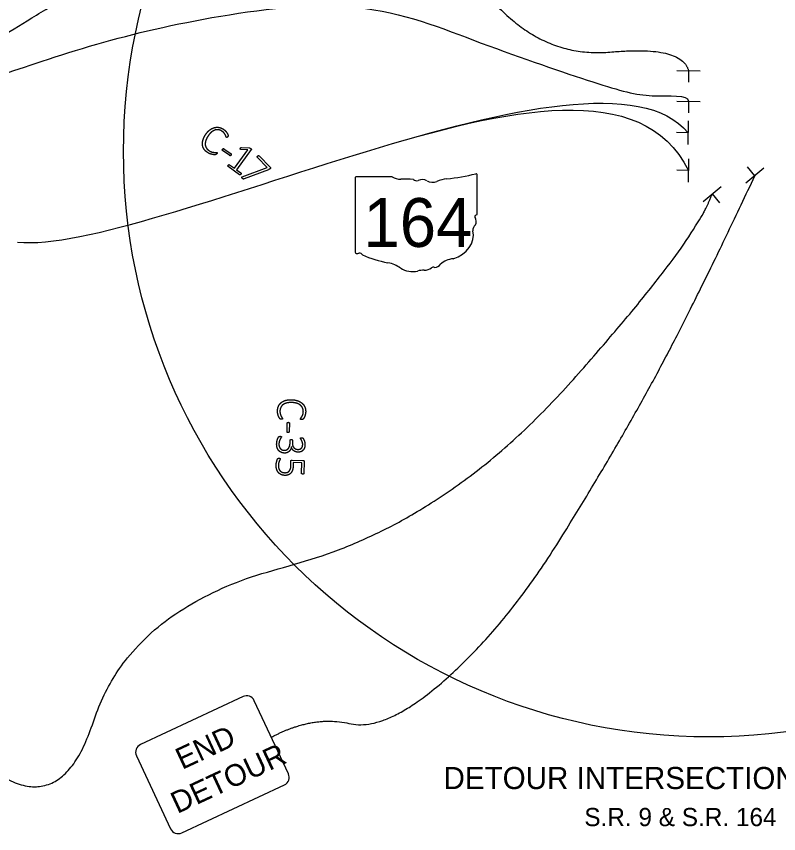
# Model space of a CAD drawing. Extents: x 0 to 1214, y 0 to 883.
# Drawn here: x 83.6 to 200.8, y 223.3 to 349 of the extents above; entities that cross this region are included whole.
import ezdxf

# ---------------------------------------------------------------- set-up
doc = ezdxf.new("R2010")
doc.units = 0
for name, color, linetype in [('GM_X_Major_Lake', 7, 'Continuous'), ('GM_X_Minor_River', 7, 'Continuous'), ('GM_X_Section', 7, 'Continuous'), ('GM_X_Township_Road_Text', 7, 'Continuous'), ('SH_Data', 7, 'Continuous')]:
    doc.layers.add(name, color=color, linetype=linetype)

msp = doc.modelspace()

# ---------------------------------------------------------------- linework, layer by layer
at = {"layer": 'GM_X_Major_Lake'}
for p, q in [((116.39, 327.55), (115.28, 328.35)), ((115.47, 328.61), (116.58, 327.81)), ((118.21, 328.81), (119.42, 328.74)), ((114.4, 327.84), (114.4, 327.84)), ((116.57, 327.63), (116.57, 327.63)), ((120.9, 327.52), (122.6, 325.77)), ((117.89, 324.62), (116.15, 325.88)), ((122.58, 325.54), (122.58, 325.54)), ((118.08, 324.69), (118.08, 324.69)), ((122.33, 325.38), (118.58, 323.97)), ((124.32, 287.02), (124.32, 287.02)), ((125.2, 285.08), (125.23, 286.46)), ((125.56, 286.45), (125.52, 285.08)), ((125.36, 284.98), (125.36, 284.98)), ((125.66, 283.37), (125.67, 283.79)), ((125.87, 282.81), (125.86, 282.81)), ((126.02, 283.78), (126.01, 283.41)), ((124.82, 281.82), (124.82, 281.82)), ((125.98, 280.74), (127.64, 280.7)), ((127.83, 280.51), (127.79, 278.7)), ((124.89, 278.39), (124.89, 278.39))]:
    msp.add_line(p, q, dxfattribs=at)
for points in [[(116.35, 326.15), (117.11, 325.6), (119.15, 328.42), (118.1, 328.5)], [(119.69, 328.48), (117.44, 325.36), (118.09, 324.89)], [(118.3, 324.29), (122.16, 325.72), (120.64, 327.27)], [(127.43, 278.71), (127.47, 280.33), (126.12, 280.36)]]:
    msp.add_lwpolyline(points, dxfattribs=at)
for points in [[(113.27, 331.46), (113.6, 331.73), (113.96, 331.84)], [(113.96, 331.84), (114.31, 331.95), (114.68, 331.9)], [(114.68, 331.9), (115.04, 331.85), (115.38, 331.63)], [(112.27, 329.93), (112.38, 330.32), (112.65, 330.75)], [(112.65, 330.75), (112.93, 331.18), (113.27, 331.46)], [(113.03, 330.53), (112.8, 330.18), (112.7, 329.85)], [(113.54, 331.14), (113.27, 330.91), (113.03, 330.53)], [(114.09, 331.47), (113.81, 331.37), (113.54, 331.14)], [(114.64, 331.53), (114.36, 331.56), (114.09, 331.47)], [(115.16, 331.33), (114.91, 331.49), (114.64, 331.53)], [(115.52, 331.02), (115.39, 331.18), (115.16, 331.33)], [(115.38, 331.63), (115.54, 331.52), (115.67, 331.4)], [(115.72, 330.71), (115.65, 330.86), (115.52, 331.02)], [(115.67, 331.4), (115.8, 331.27), (115.89, 331.14)], [(115.82, 330.47), (115.79, 330.57), (115.72, 330.71)], [(115.89, 330.34), (115.85, 330.37), (115.82, 330.47)], [(115.89, 331.14), (115.99, 331.01), (116.05, 330.88)], [(116.07, 330.45), (116.04, 330.42), (116.02, 330.39)], [(116.05, 330.88), (116.11, 330.76), (116.12, 330.7)], [(116.1, 330.52), (116.09, 330.49), (116.07, 330.45)], [(116.13, 330.57), (116.12, 330.54), (116.1, 330.52)], [(116.12, 330.7), (116.14, 330.64), (116.14, 330.61)], [(116.14, 330.61), (116.13, 330.59), (116.13, 330.57)], [(112.2, 329.18), (112.16, 329.53), (112.27, 329.93)], [(112.7, 329.85), (112.6, 329.53), (112.62, 329.25)], [(112.62, 329.25), (112.64, 328.96), (112.79, 328.73)], [(115.93, 330.33), (115.91, 330.33), (115.89, 330.34)], [(115.98, 330.35), (115.95, 330.33), (115.93, 330.33)], [(116.02, 330.39), (116, 330.36), (115.98, 330.35)], [(112.44, 328.54), (112.24, 328.83), (112.2, 329.18)], [(112.97, 328.03), (112.64, 328.24), (112.44, 328.54)], [(112.79, 328.73), (112.94, 328.49), (113.22, 328.31)], [(113.38, 327.82), (113.18, 327.89), (112.97, 328.03)], [(113.22, 328.31), (113.44, 328.17), (113.64, 328.11)], [(113.64, 328.11), (113.84, 328.06), (114.01, 328.05)], [(114.01, 328.05), (114.17, 328.05), (114.28, 328.05)], [(114.28, 328.05), (114.39, 328.06), (114.44, 328.03)], [(114.44, 328.03), (114.45, 328.02), (114.46, 328.01)], [(114.46, 327.97), (114.46, 327.95), (114.44, 327.92)], [(114.46, 328.01), (114.47, 328), (114.46, 327.97)], [(115.24, 328.42), (115.24, 328.46), (115.29, 328.54)], [(115.28, 328.35), (115.24, 328.37), (115.24, 328.42)], [(115.29, 328.54), (115.34, 328.61), (115.39, 328.63)], [(115.39, 328.63), (115.43, 328.64), (115.47, 328.61)], [(117.97, 328.56), (117.97, 328.59), (117.98, 328.62)], [(118.01, 328.52), (117.98, 328.54), (117.97, 328.56)], [(117.98, 328.62), (118, 328.65), (118.03, 328.7)], [(118.1, 328.5), (118.04, 328.51), (118.01, 328.52)], [(118.03, 328.7), (118.06, 328.73), (118.08, 328.75)], [(118.08, 328.75), (118.1, 328.78), (118.12, 328.79)], [(118.12, 328.79), (118.14, 328.8), (118.16, 328.81)], [(118.16, 328.81), (118.18, 328.81), (118.21, 328.81)], [(119.42, 328.74), (119.43, 328.74), (119.45, 328.74)], [(119.45, 328.74), (119.46, 328.73), (119.48, 328.73)], [(119.48, 328.73), (119.51, 328.72), (119.53, 328.7)], [(119.53, 328.7), (119.55, 328.69), (119.58, 328.67)], [(119.58, 328.67), (119.62, 328.63), (119.65, 328.61)], [(119.65, 328.61), (119.68, 328.58), (119.69, 328.56)], [(119.69, 328.56), (119.71, 328.53), (119.71, 328.52)], [(119.71, 328.52), (119.7, 328.5), (119.69, 328.48)], [(113.75, 327.72), (113.58, 327.75), (113.38, 327.82)], [(114.05, 327.69), (113.92, 327.69), (113.75, 327.72)], [(114.22, 327.7), (114.18, 327.69), (114.05, 327.69)], [(114.28, 327.72), (114.26, 327.71), (114.22, 327.7)], [(114.32, 327.75), (114.3, 327.73), (114.28, 327.72)], [(114.36, 327.79), (114.34, 327.76), (114.32, 327.75)], [(114.4, 327.84), (114.38, 327.81), (114.36, 327.79)], [(114.44, 327.92), (114.42, 327.88), (114.4, 327.84)], [(116.47, 327.54), (116.43, 327.52), (116.39, 327.55)], [(116.57, 327.63), (116.51, 327.55), (116.47, 327.54)], [(116.61, 327.69), (116.59, 327.66), (116.57, 327.63)], [(116.58, 327.81), (116.6, 327.8), (116.61, 327.79)], [(116.61, 327.79), (116.62, 327.77), (116.62, 327.74)], [(116.62, 327.74), (116.62, 327.72), (116.61, 327.69)], [(120.64, 327.27), (120.6, 327.32), (120.62, 327.37)], [(120.62, 327.37), (120.63, 327.43), (120.69, 327.49)], [(120.69, 327.49), (120.72, 327.52), (120.75, 327.53)], [(120.75, 327.53), (120.77, 327.55), (120.8, 327.55)], [(120.8, 327.55), (120.83, 327.56), (120.85, 327.55)], [(120.85, 327.55), (120.88, 327.54), (120.9, 327.52)], [(116.11, 325.95), (116.11, 325.97), (116.12, 326)], [(116.13, 325.91), (116.12, 325.92), (116.11, 325.95)], [(116.12, 326), (116.13, 326.04), (116.16, 326.07)], [(116.15, 325.88), (116.14, 325.89), (116.13, 325.91)], [(116.16, 326.07), (116.18, 326.11), (116.21, 326.13)], [(116.21, 326.13), (116.24, 326.15), (116.26, 326.16)], [(116.26, 326.16), (116.28, 326.17), (116.31, 326.16)], [(116.31, 326.16), (116.33, 326.16), (116.35, 326.15)], [(122.47, 325.45), (122.44, 325.43), (122.41, 325.42)], [(122.52, 325.49), (122.5, 325.47), (122.47, 325.45)], [(122.58, 325.54), (122.55, 325.51), (122.52, 325.49)], [(122.63, 325.6), (122.61, 325.57), (122.58, 325.54)], [(122.6, 325.77), (122.63, 325.74), (122.64, 325.71)], [(122.65, 325.66), (122.65, 325.63), (122.63, 325.6)], [(122.64, 325.71), (122.66, 325.69), (122.65, 325.66)], [(117.93, 324.6), (117.91, 324.61), (117.89, 324.62)], [(117.98, 324.6), (117.95, 324.6), (117.93, 324.6)], [(118.03, 324.63), (118, 324.61), (117.98, 324.6)], [(118.08, 324.69), (118.05, 324.65), (118.03, 324.63)], [(118.12, 324.75), (118.1, 324.72), (118.08, 324.69)], [(118.09, 324.89), (118.11, 324.88), (118.12, 324.85)], [(118.12, 324.85), (118.13, 324.83), (118.13, 324.81)], [(118.13, 324.81), (118.13, 324.78), (118.12, 324.75)], [(118.22, 324.22), (118.22, 324.25), (118.24, 324.26)], [(118.24, 324.16), (118.22, 324.19), (118.22, 324.22)], [(118.24, 324.26), (118.27, 324.28), (118.3, 324.29)], [(122.41, 325.42), (122.37, 325.4), (122.33, 325.38)], [(118.31, 324.07), (118.26, 324.12), (118.24, 324.16)], [(118.39, 324), (118.35, 324.02), (118.31, 324.07)], [(118.45, 323.96), (118.42, 323.97), (118.39, 324)], [(118.51, 323.95), (118.48, 323.95), (118.45, 323.96)], [(118.58, 323.97), (118.54, 323.95), (118.51, 323.95)], [(123.73, 288.33), (123.74, 288.73), (123.89, 289.05)], [(123.89, 289.05), (124.04, 289.37), (124.31, 289.59)], [(124.59, 289.27), (124.36, 289.1), (124.24, 288.85)], [(124.31, 289.59), (124.59, 289.81), (124.98, 289.93)], [(125.15, 289.52), (124.82, 289.44), (124.59, 289.27)], [(124.98, 289.93), (125.38, 290.04), (125.88, 290.03)], [(125.9, 289.59), (125.48, 289.6), (125.15, 289.52)], [(125.88, 290.03), (126.4, 290.01), (126.81, 289.87)], [(126.68, 289.48), (126.34, 289.58), (125.9, 289.59)], [(127.25, 289.18), (127.02, 289.37), (126.68, 289.48)], [(126.81, 289.87), (127.22, 289.73), (127.5, 289.49)], [(127.59, 288.75), (127.48, 289), (127.25, 289.18)], [(127.5, 289.49), (127.78, 289.24), (127.93, 288.91)], [(123.77, 287.87), (123.73, 288.08), (123.73, 288.33)], [(123.88, 287.5), (123.82, 287.66), (123.77, 287.87)], [(124.24, 288.85), (124.11, 288.59), (124.1, 288.27)], [(124.1, 288.27), (124.1, 288), (124.16, 287.8)], [(124.16, 287.8), (124.22, 287.6), (124.3, 287.46)], [(127.46, 287.4), (127.55, 287.53), (127.62, 287.73)], [(127.7, 288.2), (127.7, 288.49), (127.59, 288.75)], [(127.62, 287.73), (127.69, 287.92), (127.7, 288.2)], [(128.01, 287.8), (127.97, 287.62), (127.92, 287.47)], [(127.93, 288.91), (128.07, 288.57), (128.06, 288.17)], [(128.06, 288.17), (128.06, 287.98), (128.01, 287.8)], [(124.01, 287.24), (123.95, 287.34), (123.88, 287.5)], [(124.11, 287.1), (124.08, 287.13), (124.01, 287.24)], [(124.16, 287.05), (124.14, 287.06), (124.11, 287.1)], [(124.2, 287.03), (124.18, 287.04), (124.16, 287.05)], [(124.26, 287.02), (124.23, 287.03), (124.2, 287.03)], [(124.32, 287.02), (124.29, 287.02), (124.26, 287.02)], [(124.3, 287.46), (124.38, 287.32), (124.44, 287.23)], [(124.41, 287.02), (124.37, 287.02), (124.32, 287.02)], [(124.47, 287.03), (124.45, 287.02), (124.41, 287.02)], [(124.44, 287.23), (124.51, 287.13), (124.51, 287.09)], [(124.5, 287.05), (124.49, 287.04), (124.47, 287.03)], [(124.51, 287.09), (124.51, 287.07), (124.5, 287.05)], [(125.23, 286.46), (125.23, 286.5), (125.27, 286.53)], [(125.27, 286.53), (125.3, 286.55), (125.4, 286.55)], [(125.4, 286.55), (125.49, 286.55), (125.52, 286.52)], [(125.52, 286.52), (125.56, 286.49), (125.56, 286.45)], [(127.24, 287.06), (127.24, 287.1), (127.31, 287.18)], [(127.25, 287.02), (127.24, 287.03), (127.24, 287.06)], [(127.29, 286.99), (127.26, 287), (127.25, 287.02)], [(127.34, 286.97), (127.31, 286.98), (127.29, 286.99)], [(127.31, 287.18), (127.38, 287.27), (127.46, 287.4)], [(127.42, 286.96), (127.38, 286.96), (127.34, 286.97)], [(127.5, 286.97), (127.46, 286.96), (127.42, 286.96)], [(127.55, 286.97), (127.53, 286.97), (127.5, 286.97)], [(127.6, 286.99), (127.58, 286.98), (127.55, 286.97)], [(127.66, 287.04), (127.62, 287), (127.6, 286.99)], [(127.78, 287.21), (127.71, 287.09), (127.66, 287.04)], [(127.92, 287.47), (127.86, 287.32), (127.78, 287.21)], [(123.65, 283.65), (123.69, 283.84), (123.74, 283.98)], [(123.74, 283.98), (123.79, 284.12), (123.85, 284.21)], [(123.85, 284.21), (123.9, 284.31), (123.92, 284.33)], [(123.92, 284.33), (123.94, 284.35), (123.96, 284.36)], [(123.96, 284.36), (123.98, 284.37), (124, 284.38)], [(124, 284.38), (124.03, 284.39), (124.07, 284.39)], [(124.14, 283.97), (124.07, 283.82), (124.01, 283.64)], [(124.07, 284.39), (124.1, 284.4), (124.16, 284.4)], [(124.27, 284.2), (124.21, 284.11), (124.14, 283.97)], [(124.16, 284.4), (124.26, 284.39), (124.29, 284.37)], [(124.33, 284.31), (124.32, 284.28), (124.27, 284.2)], [(124.29, 284.37), (124.33, 284.35), (124.33, 284.31)], [(125.23, 285.01), (125.2, 285.04), (125.2, 285.08)], [(125.36, 284.98), (125.26, 284.99), (125.23, 285.01)], [(125.44, 284.99), (125.4, 284.98), (125.36, 284.98)], [(125.49, 285.01), (125.47, 284.99), (125.44, 284.99)], [(125.52, 285.04), (125.51, 285.02), (125.49, 285.01)], [(125.52, 285.08), (125.52, 285.06), (125.52, 285.04)], [(127.25, 284.11), (127.25, 284.13), (127.26, 284.14)], [(127.31, 283.99), (127.25, 284.08), (127.25, 284.11)], [(127.26, 284.14), (127.26, 284.16), (127.28, 284.17)], [(127.28, 284.17), (127.3, 284.18), (127.34, 284.19)], [(127.43, 283.78), (127.36, 283.91), (127.31, 283.99)], [(127.34, 284.19), (127.37, 284.19), (127.43, 284.19)], [(127.43, 284.19), (127.47, 284.19), (127.49, 284.19)], [(127.49, 284.19), (127.52, 284.18), (127.54, 284.17)], [(127.54, 284.17), (127.57, 284.16), (127.59, 284.15)], [(127.59, 284.15), (127.61, 284.13), (127.64, 284.1)], [(127.64, 284.1), (127.67, 284.07), (127.72, 283.98)], [(127.72, 283.98), (127.78, 283.89), (127.83, 283.75)], [(123.6, 283.26), (123.6, 283.47), (123.65, 283.65)], [(123.68, 282.65), (123.59, 282.91), (123.6, 283.26)], [(124.01, 283.64), (123.95, 283.45), (123.95, 283.22)], [(123.95, 283.22), (123.94, 282.99), (124, 282.81)], [(124, 282.81), (124.06, 282.63), (124.17, 282.51)], [(125.4, 282.54), (125.52, 282.68), (125.59, 282.89)], [(125.59, 282.89), (125.66, 283.11), (125.66, 283.37)], [(125.67, 283.79), (125.67, 283.81), (125.68, 283.83)], [(125.68, 283.83), (125.69, 283.85), (125.72, 283.87)], [(125.72, 283.87), (125.74, 283.89), (125.77, 283.9)], [(125.86, 282.81), (125.84, 282.59), (125.75, 282.41)], [(125.77, 283.9), (125.8, 283.91), (125.85, 283.91)], [(125.85, 283.91), (125.9, 283.91), (125.93, 283.9)], [(125.99, 282.46), (125.9, 282.61), (125.87, 282.81)], [(125.93, 283.9), (125.96, 283.89), (125.98, 283.87)], [(125.98, 283.87), (126, 283.85), (126.01, 283.83)], [(126.01, 283.83), (126.02, 283.81), (126.02, 283.78)], [(126.01, 283.41), (126, 283.18), (126.06, 282.99)], [(126.06, 282.99), (126.12, 282.81), (126.23, 282.67)], [(127.38, 282.56), (127.48, 282.65), (127.54, 282.79)], [(127.55, 283.49), (127.5, 283.66), (127.43, 283.78)], [(127.54, 282.79), (127.6, 282.94), (127.6, 283.13)], [(127.6, 283.13), (127.61, 283.33), (127.55, 283.49)], [(127.83, 283.75), (127.88, 283.62), (127.92, 283.45)], [(127.95, 283.08), (127.94, 282.79), (127.86, 282.58)], [(127.92, 283.45), (127.95, 283.28), (127.95, 283.08)], [(123.92, 282.2), (123.76, 282.38), (123.68, 282.65)], [(124.31, 281.92), (124.09, 282.02), (123.92, 282.2)], [(124.17, 282.51), (124.28, 282.38), (124.43, 282.32)], [(124.82, 281.82), (124.54, 281.83), (124.31, 281.92)], [(124.43, 282.32), (124.59, 282.25), (124.77, 282.25)], [(124.77, 282.25), (124.97, 282.24), (125.13, 282.32)], [(125.2, 281.89), (125.02, 281.81), (124.82, 281.82)], [(125.13, 282.32), (125.29, 282.39), (125.4, 282.54)], [(125.52, 282.09), (125.38, 281.96), (125.2, 281.89)], [(125.75, 282.41), (125.66, 282.23), (125.52, 282.09)], [(126.21, 282.2), (126.07, 282.3), (125.99, 282.46)], [(126.52, 282.03), (126.34, 282.09), (126.21, 282.2)], [(126.23, 282.67), (126.35, 282.54), (126.51, 282.47)], [(126.51, 282.47), (126.67, 282.39), (126.87, 282.39)], [(126.89, 281.97), (126.69, 281.97), (126.52, 282.03)], [(126.87, 282.39), (127.01, 282.38), (127.15, 282.43)], [(127.3, 282.02), (127.11, 281.96), (126.89, 281.97)], [(127.15, 282.43), (127.28, 282.47), (127.38, 282.56)], [(127.63, 282.23), (127.49, 282.09), (127.3, 282.02)], [(127.86, 282.58), (127.78, 282.36), (127.63, 282.23)], [(123.52, 279.96), (123.53, 280.16), (123.56, 280.33)], [(123.56, 280.33), (123.6, 280.51), (123.64, 280.65)], [(123.64, 280.65), (123.68, 280.78), (123.73, 280.87)], [(123.73, 280.87), (123.77, 280.95), (123.79, 280.98)], [(123.79, 280.98), (123.81, 281), (123.83, 281.01)], [(123.83, 281.01), (123.84, 281.01), (123.87, 281.02)], [(123.87, 281.02), (123.89, 281.03), (123.92, 281.03)], [(123.92, 280.35), (123.87, 280.17), (123.87, 279.93)], [(123.92, 281.03), (123.95, 281.03), (123.99, 281.03)], [(124.02, 280.65), (123.97, 280.53), (123.92, 280.35)], [(123.99, 281.03), (124.03, 281.03), (124.06, 281.02)], [(124.12, 280.84), (124.08, 280.77), (124.02, 280.65)], [(124.06, 281.02), (124.1, 281.02), (124.12, 281.01)], [(124.12, 281.01), (124.14, 280.99), (124.15, 280.98)], [(124.16, 280.94), (124.16, 280.91), (124.12, 280.84)], [(124.15, 280.98), (124.16, 280.96), (124.16, 280.94)], [(125.77, 280.58), (125.78, 280.66), (125.82, 280.7)], [(125.79, 280.32), (125.77, 280.46), (125.77, 280.58)], [(125.8, 279.98), (125.81, 280.18), (125.79, 280.32)], [(125.82, 280.7), (125.86, 280.74), (125.98, 280.74)], [(126.12, 280.36), (126.14, 280.25), (126.14, 280.12)], [(127.64, 280.7), (127.74, 280.7), (127.78, 280.64)], [(127.78, 280.64), (127.83, 280.59), (127.83, 280.51)], [(123.6, 279.33), (123.51, 279.62), (123.52, 279.96)], [(123.86, 278.84), (123.69, 279.05), (123.6, 279.33)], [(123.87, 279.93), (123.86, 279.69), (123.91, 279.49)], [(123.91, 279.49), (123.97, 279.29), (124.09, 279.14)], [(124.09, 279.14), (124.21, 278.99), (124.4, 278.9)], [(125.26, 278.87), (125.44, 278.94), (125.55, 279.08)], [(125.55, 279.08), (125.67, 279.23), (125.73, 279.45)], [(125.73, 279.45), (125.8, 279.67), (125.8, 279.98)], [(126.03, 279.18), (125.93, 278.91), (125.77, 278.73)], [(126.13, 279.83), (126.13, 279.46), (126.03, 279.18)], [(126.14, 280.12), (126.14, 280), (126.13, 279.83)], [(124.3, 278.51), (124.04, 278.63), (123.86, 278.84)], [(124.89, 278.39), (124.55, 278.4), (124.3, 278.51)], [(124.4, 278.9), (124.59, 278.81), (124.86, 278.81)], [(124.86, 278.81), (125.09, 278.8), (125.26, 278.87)], [(125.38, 278.47), (125.15, 278.38), (124.89, 278.39)], [(125.77, 278.73), (125.6, 278.55), (125.38, 278.47)], [(127.48, 278.62), (127.43, 278.65), (127.43, 278.71)], [(127.61, 278.59), (127.53, 278.59), (127.48, 278.62)], [(127.69, 278.59), (127.65, 278.59), (127.61, 278.59)], [(127.74, 278.62), (127.72, 278.6), (127.69, 278.59)], [(127.78, 278.65), (127.76, 278.63), (127.74, 278.62)], [(127.79, 278.7), (127.79, 278.68), (127.78, 278.65)]]:
    msp.add_open_spline(points, degree=2, dxfattribs=at)
at = {"layer": 'GM_X_Minor_River'}
for p, q in [((185.12, 340.66), (188.72, 340.6)), ((186.92, 340.63), (186.9, 338.83)), ((185.12, 335.94), (188.72, 335.89)), ((186.92, 335.92), (186.9, 334.12)), ((186.88, 332.88), (186.83, 329.28)), ((186.86, 331.08), (185.06, 331.11)), ((186.92, 327.08), (186.87, 323.48)), ((198.5, 325.62), (195.74, 323.31)), ((197.12, 324.46), (195.97, 325.85)), ((186.9, 325.28), (185.1, 325.3)), ((189.16, 320.51), (191.93, 322.8)), ((190.55, 321.66), (191.69, 320.27))]:
    msp.add_line(p, q, dxfattribs=at)
for points in [[(118.43, 244.39), (102.67, 237.03)], [(125.41, 232.53), (120.16, 243.76)], [(102.04, 235.3), (107.29, 224.07)], [(109.01, 223.44), (124.78, 230.8)]]:
    msp.add_lwpolyline(points, dxfattribs=at)
for centre, start, end in [((118.98, 243.21), 25.0288, 115.0288), ((103.22, 235.85), 115.0288, 205.0288), ((124.23, 231.98), 295.0288, 25.0288), ((108.46, 224.62), 205.0288, 295.0288)]:
    msp.add_arc(centre, 1.3, start, end, dxfattribs=at)
at = {"layer": 'GM_X_Township_Road_Text'}
for p, q in [((141.36, 324.29), (135.87, 324.29)), ((154.43, 318.62), (154.43, 324.58)), ((135.69, 324.1), (135.69, 312.71)), ((154.43, 318.62), (154.43, 318.62))]:
    msp.add_line(p, q, dxfattribs=at)
for centre, major_axis, start_param, end_param in [((135.9, 324.12), (0.217, 0), 1.712693, 3.28349), ((142.67, 325.62), (2.11, 0), 4.042523, 4.731795), ((147.76, 339.82), (19.88, 0), 4.814394, 5.042369), ((154.23, 324.6), (0.209, 0), 6.141152, 7.989035), ((143.37, 317.9), (7.56, 0), 1.404758, 1.657858), ((145.08, 324.18), (0.608, 0), 3.836095, 5.185415), ((145.98, 322.87), (1.26, 0), 0.950623, 2.079405), ((147.61, 324.67), (1.52, 0), 4.081561, 5.145723), ((150.29, 320.82), (4, 0), 1.699011, 2.107814), ((154.39, 318.18), (0.323, 0), 1.883978, 3.671073), ((152.33, 317.43), (1.94, 0), 5.934695, 6.695948), ((154.21, 318.6), (0.223, 0), 5.05454, 6.418171), ((155.18, 316.13), (1.41, 0), 2.387724, 3.262537), ((148.87, 315.37), (4.97, 0), 5.101752, 6.440018), ((135.9, 312.69), (0.219, 0), 3.00124, 4.508301), ((135.94, 313.85), (1.67, 0), 4.665946, 4.897461), ((136.28, 312.06), (0.603, 0), 0.519207, 1.627899), ((143.89, 322.29), (14.36, 0), 4.195997, 4.488961), ((150.97, 309.52), (2.72, 0), 1.647645, 2.488434), ((139.61, 307.6), (4.49, 0), 0.823519, 1.323587), ((147.7, 310.05), (0.428, 0), 1.147584, 2.315152), ((147.52, 311.61), (1.61, 0), 4.937069, 5.64225), ((144.47, 312), (2.85, 0), 4.026481, 4.996735), ((146.12, 308.06), (2.34, 0), 1.495662, 1.94098), ((146.32, 311.15), (1.52, 0), 4.691044, 5.507374)]:
    msp.add_ellipse(centre, major_axis=major_axis, ratio=0.8, start_param=start_param, end_param=end_param, dxfattribs=at)
at = {"layer": 'SH_Data'}
msp.add_circle((190.05, 328.19), 90, dxfattribs=at)
for points, degree in [([(67.58, 353.44), (67.58, 345.59), (76.87, 342.33), (95.84, 355.67), (148.43, 361.31), (164.28, 342.48), (185.84, 344.48), (186.92, 340.63)], 2), ([(67.58, 353.44), (67.58, 342.16), (77.81, 338.76), (77.81, 338.76), (94.68, 344.6), (112.52, 348.98), (137.16, 352.06), (154.68, 344.76), (174.38, 338.08), (180.94, 336.28), (186.91, 337.01), (186.92, 335.92)], 3), ([(83.74, 314.24), (93.83, 313.33), (137.97, 329.98), (179.84, 339.53), (186.86, 331.08)], 3), ([(83.74, 314.24), (93.83, 313.33), (137.97, 329.98), (179.84, 339.53), (186.9, 325.28)], 3), ([(122.79, 238.15), (129.22, 241.56), (140.45, 238.92), (158.98, 255.4), (175.39, 281.74), (187.66, 304.3), (197.12, 324.46)], 2), ([(76.02, 236.42), (89.73, 222.86), (101.11, 258.18), (149, 270.58), (187.94, 314.1), (190.55, 321.66)], 2)]:
    msp.add_open_spline(points, degree=degree, dxfattribs=at)

# ---------------------------------------------------------------- texts
at = {"layer": 'GM_X_Minor_River'}
for s, p in [('END', (109.07, 233.1)), ('DETOUR', (108.33, 226.33))]:
    msp.add_text(s, height=3.333, rotation=25.0288, dxfattribs=at).set_placement(p)
at = {"layer": 'GM_X_Section'}
for s, height, p in [('DETOUR INTERSECTION DETAIL 5', 3.4, (149.25, 230.17)), ('S.R. 9 & S.R. 164', 2.8, (170.9, 224.47))]:
    msp.add_text(s, height=height, dxfattribs=at).set_placement(p)
at = {"layer": 'GM_X_Township_Road_Text'}
msp.add_text('164', height=7.5, dxfattribs=at).set_placement((136.95, 313.52))

doc.saveas('drawing.dxf')
